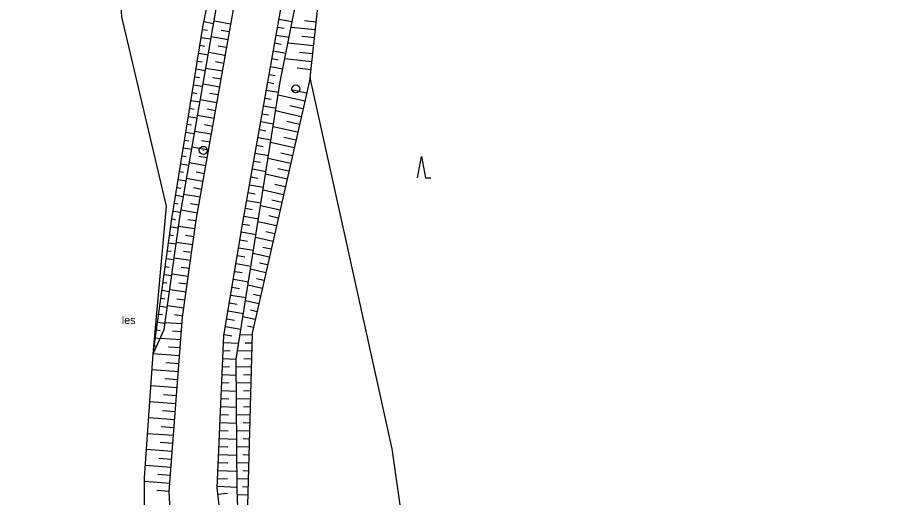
# Model space of a CAD drawing. Extents: x -762483 to -761175, y -1154655 to -1152452.
# Drawn here: x -761535.1 to -761452.1, y -1153544 to -1153499 of the extents above; entities that cross this region are included whole.
import ezdxf

# ---------------------------------------------------------------- set-up
doc = ezdxf.new("R2010")
doc.units = 0
for name, color, linetype in [('MAP_ZN_BP', 7, 'Continuous'), ('ROZHRANÍ_PLOCH', 7, 'Continuous'), ('VÝŠKOPIS', 7, 'Continuous'), ('ZELEŇ', 7, 'Continuous'), ('ZN_KULTUR', 7, 'Continuous')]:
    doc.layers.add(name, color=color, linetype=linetype)

msp = doc.modelspace()

# ---------------------------------------------------------------- linework, layer by layer
at = {"layer": 'MAP_ZN_BP'}
for centre, radius in [((-761509.05, -1153505.69), 0.375), ((-761509.05, -1153505.69), 0.0005), ((-761517.73, -1153511.451), 0.375), ((-761517.73, -1153511.451), 0.0005)]:
    msp.add_circle(centre, radius, dxfattribs=at)
at = {"layer": 'ROZHRANÍ_PLOCH'}
for points in [[(-761473.21, -1153684.07), (-761469.46, -1153679.5), (-761466.97, -1153675.46), (-761465.27, -1153671.92), (-761464.53, -1153668.61), (-761464.73, -1153664.68), (-761466, -1153658.71), (-761468.55, -1153651.77), (-761473.7, -1153641.76), (-761483.81, -1153624.91), (-761489.13, -1153616.22), (-761501.02, -1153596.18), (-761505.16, -1153588.62), (-761508.76, -1153581.79), (-761515.86, -1153566.65), (-761518.43, -1153558.82), (-761520.62, -1153549.31), (-761520.92, -1153543.45), (-761519.67, -1153527.09), (-761518.4, -1153518.01), (-761514.9, -1153498.24), (-761512.46, -1153485.54), (-761510.57, -1153476.01), (-761507.02, -1153459.49)], [(-761452.11, -1153680.09), (-761455.06, -1153677.36), (-761457.46, -1153672.86), (-761459.23, -1153668.13), (-761461.75, -1153656.48), (-761464.72, -1153649.83), (-761470.08, -1153639.37), (-761481.24, -1153620.57), (-761493.92, -1153599.29), (-761502.78, -1153583.29), (-761511.19, -1153565.87), (-761514.81, -1153554.8), (-761515.74, -1153549.15), (-761516.42, -1153543.11), (-761515.79, -1153528.81), (-761514.01, -1153518.23), (-761510.25, -1153496.92), (-761507.85, -1153485.44), (-761506.02, -1153476.2), (-761502.85, -1153460.41)]]:
    msp.add_lwpolyline(points, dxfattribs=at)
at = {"layer": 'VÝŠKOPIS'}
for p, q in [((-761517.66, -1153499.383), (-761516.761, -1153499.57)), ((-761515.142, -1153499.609), (-761516.719, -1153499.329)), ((-761510.645, -1153499.161), (-761509.385, -1153499.384)), ((-761507.151, -1153499.421), (-761508.248, -1153499.301)), ((-761517.795, -1153500.121), (-761517.339, -1153500.195)), ((-761515.273, -1153500.347), (-761516.061, -1153500.208)), ((-761510.776, -1153499.9), (-761510.154, -1153500.01)), ((-761507.232, -1153500.166), (-761509.492, -1153499.92)), ((-761517.915, -1153500.861), (-761517.012, -1153501.008)), ((-761515.404, -1153501.086), (-761516.977, -1153500.807)), ((-761510.906, -1153500.638), (-761509.678, -1153500.855)), ((-761507.314, -1153500.912), (-761508.476, -1153500.785)), ((-761518.036, -1153501.601), (-761517.588, -1153501.674)), ((-761515.535, -1153501.824), (-761516.32, -1153501.685)), ((-761511.036, -1153501.377), (-761510.431, -1153501.484)), ((-761507.395, -1153501.658), (-761509.786, -1153501.397)), ((-761518.156, -1153502.342), (-761517.269, -1153502.486)), ((-761515.665, -1153502.563), (-761517.234, -1153502.285)), ((-761511.167, -1153502.116), (-761509.971, -1153502.326)), ((-761507.476, -1153502.403), (-761508.705, -1153502.269)), ((-761518.276, -1153503.082), (-761517.837, -1153503.153)), ((-761515.796, -1153503.301), (-761516.58, -1153503.163)), ((-761511.427, -1153503.593), (-761510.265, -1153503.798)), ((-761511.297, -1153502.854), (-761510.707, -1153502.958)), ((-761507.557, -1153503.149), (-761510.08, -1153502.874)), ((-761518.397, -1153503.822), (-761517.527, -1153503.964)), ((-761515.927, -1153504.04), (-761517.492, -1153503.763)), ((-761511.558, -1153504.331), (-761510.984, -1153504.432)), ((-761507.639, -1153503.894), (-761508.933, -1153503.753)), ((-761518.517, -1153504.562), (-761518.086, -1153504.632)), ((-761516.188, -1153505.517), (-761517.749, -1153505.24)), ((-761516.058, -1153504.778), (-761516.839, -1153504.64)), ((-761511.688, -1153505.07), (-761511.118, -1153505.17)), ((-761518.758, -1153506.043), (-761518.335, -1153506.112)), ((-761518.637, -1153505.303), (-761517.784, -1153505.441)), ((-761516.319, -1153506.255), (-761517.098, -1153506.117)), ((-761511.818, -1153505.808), (-761510.666, -1153506.012)), ((-761508.051, -1153506.103), (-761509.32, -1153505.816)), ((-761518.878, -1153506.783), (-761518.042, -1153506.919)), ((-761516.45, -1153506.994), (-761518.007, -1153506.718)), ((-761511.949, -1153506.547), (-761511.366, -1153506.65)), ((-761508.217, -1153506.835), (-761510.707, -1153506.271)), ((-761518.998, -1153507.524), (-761518.584, -1153507.591)), ((-761516.58, -1153507.732), (-761517.358, -1153507.595)), ((-761512.079, -1153507.286), (-761510.902, -1153507.493)), ((-761508.548, -1153508.298), (-761510.944, -1153507.755)), ((-761508.382, -1153507.566), (-761509.604, -1153507.29)), ((-761519.119, -1153508.264), (-761518.299, -1153508.397)), ((-761516.711, -1153508.471), (-761518.264, -1153508.196)), ((-761512.209, -1153508.024), (-761511.615, -1153508.129)), ((-761519.239, -1153509.004), (-761518.833, -1153509.07)), ((-761516.842, -1153509.209), (-761517.617, -1153509.072)), ((-761512.34, -1153508.763), (-761511.138, -1153508.975)), ((-761508.879, -1153509.761), (-761511.18, -1153509.24)), ((-761508.713, -1153509.029), (-761509.888, -1153508.763)), ((-761519.359, -1153509.744), (-761518.556, -1153509.875)), ((-761516.973, -1153509.948), (-761518.521, -1153509.674)), ((-761512.6, -1153510.24), (-761511.374, -1153510.456)), ((-761512.47, -1153509.501), (-761511.863, -1153509.609)), ((-761509.044, -1153510.492), (-761510.171, -1153510.237)), ((-761519.48, -1153510.485), (-761519.082, -1153510.549)), ((-761517.103, -1153510.686), (-761517.877, -1153510.55)), ((-761512.731, -1153510.979), (-761512.111, -1153511.088)), ((-761509.21, -1153511.224), (-761511.416, -1153510.724)), ((-761519.6, -1153511.225), (-761518.814, -1153511.353)), ((-761517.234, -1153511.425), (-761518.779, -1153511.151)), ((-761512.861, -1153511.717), (-761511.61, -1153511.938)), ((-761509.375, -1153511.955), (-761510.455, -1153511.711)), ((-761519.841, -1153512.706), (-761519.071, -1153512.831)), ((-761519.72, -1153511.965), (-761519.331, -1153512.028)), ((-761517.496, -1153512.902), (-761519.036, -1153512.629)), ((-761517.365, -1153512.163), (-761518.136, -1153512.027)), ((-761512.991, -1153512.456), (-761512.359, -1153512.567)), ((-761509.541, -1153512.687), (-761511.653, -1153512.209)), ((-761519.961, -1153513.446), (-761519.58, -1153513.508)), ((-761517.626, -1153513.64), (-761518.396, -1153513.504)), ((-761513.122, -1153513.194), (-761511.845, -1153513.42)), ((-761509.707, -1153513.418), (-761510.739, -1153513.184)), ((-761520.081, -1153514.186), (-761519.329, -1153514.308)), ((-761517.757, -1153514.379), (-761519.294, -1153514.107)), ((-761513.252, -1153513.933), (-761512.608, -1153514.047)), ((-761509.872, -1153514.15), (-761511.889, -1153513.693)), ((-761520.202, -1153514.926), (-761519.83, -1153514.987)), ((-761517.888, -1153515.118), (-761518.655, -1153514.982)), ((-761513.382, -1153514.672), (-761512.081, -1153514.901)), ((-761510.203, -1153515.613), (-761512.125, -1153515.178)), ((-761510.038, -1153514.881), (-761511.022, -1153514.658)), ((-761520.322, -1153515.667), (-761519.586, -1153515.786)), ((-761518.019, -1153515.856), (-761519.551, -1153515.585)), ((-761513.512, -1153515.41), (-761512.856, -1153515.526)), ((-761520.442, -1153516.407), (-761520.079, -1153516.466)), ((-761518.149, -1153516.595), (-761518.915, -1153516.459)), ((-761513.773, -1153516.887), (-761513.104, -1153517.005)), ((-761513.643, -1153516.149), (-761512.317, -1153516.383)), ((-761510.534, -1153517.076), (-761512.361, -1153516.662)), ((-761510.369, -1153516.344), (-761511.306, -1153516.132)), ((-761520.563, -1153517.147), (-761519.844, -1153517.264)), ((-761518.28, -1153517.333), (-761519.808, -1153517.063)), ((-761513.903, -1153517.626), (-761512.553, -1153517.864)), ((-761510.7, -1153517.807), (-761511.59, -1153517.606)), ((-761520.682, -1153517.888), (-761520.322, -1153517.937)), ((-761518.409, -1153518.072), (-761519.176, -1153517.965)), ((-761514.033, -1153518.365), (-761513.351, -1153518.479)), ((-761510.865, -1153518.539), (-761512.598, -1153518.146)), ((-761520.886, -1153519.374), (-761520.526, -1153519.423)), ((-761520.784, -1153518.631), (-761520.064, -1153518.729)), ((-761518.513, -1153518.815), (-761520.046, -1153518.6)), ((-761514.157, -1153519.104), (-761512.787, -1153519.335)), ((-761511.031, -1153519.27), (-761511.873, -1153519.079)), ((-761520.987, -1153520.117), (-761520.269, -1153520.215)), ((-761518.72, -1153520.3), (-761520.252, -1153520.086)), ((-761518.616, -1153519.557), (-761519.383, -1153519.45)), ((-761514.282, -1153519.844), (-761513.593, -1153519.96)), ((-761511.196, -1153520.002), (-761512.834, -1153519.631)), ((-761521.089, -1153520.86), (-761520.73, -1153520.909)), ((-761518.824, -1153521.043), (-761519.589, -1153520.936)), ((-761514.406, -1153520.584), (-761513.023, -1153520.816)), ((-761511.362, -1153520.733), (-761512.157, -1153520.553)), ((-761521.191, -1153521.603), (-761520.475, -1153521.701)), ((-761518.928, -1153521.786), (-761520.457, -1153521.572)), ((-761514.53, -1153521.323), (-761513.835, -1153521.44)), ((-761511.527, -1153521.465), (-761513.07, -1153521.115)), ((-761521.292, -1153522.346), (-761520.935, -1153522.395)), ((-761519.032, -1153522.529), (-761519.796, -1153522.422)), ((-761514.655, -1153522.063), (-761513.258, -1153522.298)), ((-761511.859, -1153522.928), (-761513.307, -1153522.6)), ((-761511.693, -1153522.196), (-761512.441, -1153522.027)), ((-761521.394, -1153523.089), (-761520.68, -1153523.187)), ((-761519.136, -1153523.271), (-761520.662, -1153523.058)), ((-761514.904, -1153523.542), (-761513.494, -1153523.779)), ((-761514.779, -1153522.802), (-761514.078, -1153522.92)), ((-761512.024, -1153523.659), (-761512.724, -1153523.501)), ((-761521.495, -1153523.832), (-761521.139, -1153523.881)), ((-761519.24, -1153524.014), (-761520.002, -1153523.907)), ((-761515.028, -1153524.282), (-761514.32, -1153524.401)), ((-761512.19, -1153524.391), (-761513.543, -1153524.084)), ((-761521.597, -1153524.575), (-761520.886, -1153524.673)), ((-761519.344, -1153524.757), (-761520.868, -1153524.544)), ((-761515.153, -1153525.021), (-761513.73, -1153525.26)), ((-761512.355, -1153525.122), (-761513.008, -1153524.974)), ((-761521.699, -1153525.318), (-761521.343, -1153525.367)), ((-761519.551, -1153526.242), (-761521.073, -1153526.03)), ((-761519.448, -1153525.5), (-761520.209, -1153525.393)), ((-761515.277, -1153525.761), (-761514.562, -1153525.881)), ((-761512.521, -1153525.854), (-761513.779, -1153525.569)), ((-761521.902, -1153526.805), (-761521.548, -1153526.853)), ((-761521.8, -1153526.062), (-761521.091, -1153526.159)), ((-761519.655, -1153526.985), (-761520.416, -1153526.879)), ((-761515.401, -1153526.5), (-761513.966, -1153526.742)), ((-761512.686, -1153526.585), (-761513.292, -1153526.448)), ((-761522.004, -1153527.548), (-761521.296, -1153527.644)), ((-761519.719, -1153527.732), (-761521.292, -1153527.612)), ((-761515.526, -1153527.24), (-761514.805, -1153527.361)), ((-761512.852, -1153527.317), (-761514.015, -1153527.053)), ((-761522.105, -1153528.291), (-761521.772, -1153528.336)), ((-761519.776, -1153528.48), (-761520.602, -1153528.417)), ((-761515.65, -1153527.98), (-761514.202, -1153528.223)), ((-761513.017, -1153528.048), (-761513.575, -1153527.922)), ((-761522.207, -1153529.034), (-761521.763, -1153529.094)), ((-761519.833, -1153529.228), (-761521.757, -1153529.081)), ((-761515.775, -1153528.719), (-761515.047, -1153528.842)), ((-761513.145, -1153528.784), (-761514.286, -1153528.753)), ((-761522.308, -1153529.777), (-761522.197, -1153529.792)), ((-761519.89, -1153529.976), (-761520.989, -1153529.892)), ((-761515.819, -1153529.467), (-761514.41, -1153529.529)), ((-761513.166, -1153529.534), (-761513.785, -1153529.517)), ((-761519.948, -1153530.724), (-761522.411, -1153530.535)), ((-761515.885, -1153530.966), (-761514.647, -1153531.02)), ((-761515.852, -1153530.217), (-761515.19, -1153530.246)), ((-761513.186, -1153530.284), (-761514.524, -1153530.247)), ((-761513.207, -1153531.033), (-761513.925, -1153531.014)), ((-761520.005, -1153531.471), (-761521.234, -1153531.377)), ((-761515.918, -1153531.715), (-761515.281, -1153531.743)), ((-761513.227, -1153531.783), (-761514.644, -1153531.745)), ((-761520.062, -1153532.219), (-761522.515, -1153532.032)), ((-761515.951, -1153532.464), (-761514.637, -1153532.522)), ((-761513.247, -1153532.533), (-761513.942, -1153532.514)), ((-761520.119, -1153532.967), (-761521.343, -1153532.874)), ((-761515.984, -1153533.214), (-761515.307, -1153533.243)), ((-761513.268, -1153533.283), (-761514.63, -1153533.246)), ((-761520.176, -1153533.715), (-761522.62, -1153533.528)), ((-761516.017, -1153533.963), (-761514.623, -1153534.024)), ((-761513.288, -1153534.032), (-761513.956, -1153534.014)), ((-761520.29, -1153535.21), (-761522.724, -1153535.025)), ((-761520.233, -1153534.463), (-761521.452, -1153534.37)), ((-761516.05, -1153534.712), (-761515.333, -1153534.744)), ((-761513.309, -1153534.782), (-761514.617, -1153534.746)), ((-761520.348, -1153535.958), (-761521.562, -1153535.866)), ((-761516.083, -1153535.461), (-761514.61, -1153535.526)), ((-761513.329, -1153535.532), (-761513.97, -1153535.514)), ((-761520.405, -1153536.706), (-761522.828, -1153536.521)), ((-761516.116, -1153536.211), (-761515.36, -1153536.244)), ((-761513.349, -1153536.282), (-761514.603, -1153536.247)), ((-761520.462, -1153537.454), (-761521.671, -1153537.362)), ((-761516.149, -1153536.96), (-761514.596, -1153537.028)), ((-761513.37, -1153537.031), (-761513.983, -1153537.015)), ((-761520.519, -1153538.202), (-761522.932, -1153538.017)), ((-761516.215, -1153538.459), (-761514.583, -1153538.53)), ((-761516.182, -1153537.709), (-761515.386, -1153537.744)), ((-761513.39, -1153537.781), (-761514.59, -1153537.748)), ((-761520.576, -1153538.95), (-761521.78, -1153538.858)), ((-761516.248, -1153539.208), (-761515.412, -1153539.245)), ((-761513.431, -1153539.28), (-761514.577, -1153539.249)), ((-761513.411, -1153538.531), (-761513.997, -1153538.515)), ((-761520.633, -1153539.697), (-761523.036, -1153539.514)), ((-761516.281, -1153539.957), (-761514.57, -1153540.033)), ((-761513.452, -1153540.03), (-761514.011, -1153540.015)), ((-761520.69, -1153540.445), (-761521.889, -1153540.354)), ((-761516.314, -1153540.706), (-761515.439, -1153540.745)), ((-761513.472, -1153540.78), (-761514.563, -1153540.75)), ((-761520.748, -1153541.193), (-761523.141, -1153541.01)), ((-761516.347, -1153541.456), (-761514.556, -1153541.535)), ((-761513.492, -1153541.53), (-761514.024, -1153541.515)), ((-761520.862, -1153542.689), (-761523.219, -1153542.509)), ((-761520.805, -1153541.941), (-761521.999, -1153541.85)), ((-761516.38, -1153542.205), (-761515.465, -1153542.245)), ((-761513.513, -1153542.279), (-761514.55, -1153542.251)), ((-761520.919, -1153543.437), (-761522.067, -1153543.349)), ((-761516.413, -1153542.954), (-761514.543, -1153543.037)), ((-761513.533, -1153543.029), (-761514.038, -1153543.015)), ((-761516.354, -1153543.7), (-761515.444, -1153543.598)), ((-761513.554, -1153543.779), (-761514.525, -1153543.752))]:
    msp.add_line(p, q, dxfattribs=at)
for points in [[(-761522.41, -1153530.52), (-761520.68, -1153517.87), (-761517.73, -1153499.72), (-761512.59, -1153474.98), (-761507.83, -1153454.54)], [(-761522.41, -1153530.52), (-761521.38, -1153528.25), (-761519.93, -1153517.76), (-761516.46, -1153497.84), (-761512.68, -1153479.49), (-761508.08, -1153459.32)], [(-761510.51, -1153505.03), (-761506.83, -1153486.56), (-761501.96, -1153460.76)], [(-761472.39, -1153633.33), (-761479.86, -1153619.77), (-761492.52, -1153598.23), (-761505.34, -1153575.01), (-761509.58, -1153565.6), (-761513.83, -1153553.93), (-761514.33, -1153548.93), (-761514.54, -1153543.35), (-761514.65, -1153531.04), (-761510.51, -1153505.03)], [(-761507.72, -1153504.64), (-761513.14, -1153528.59), (-761513.83, -1153553.93)]]:
    msp.add_lwpolyline(points, dxfattribs=at)
at = {"layer": 'ZELEŇ'}
msp.add_line((-761523.22, -1153542.15), (-761522.41, -1153530.52), dxfattribs=at)
for points in [[(-761522.41, -1153530.52), (-761521.16, -1153516.7), (-761525.36, -1153498.92), (-761526.95, -1153474.42), (-761535, -1153440.98), (-761535.12, -1153438.71)], [(-761507.72, -1153504.64), (-761505.65, -1153485.65), (-761501.02, -1153460.93)], [(-761472.39, -1153633.33), (-761479.21, -1153619.43), (-761487.13, -1153604.92), (-761490.34, -1153596.71), (-761495.72, -1153569.61), (-761500.02, -1153539.43), (-761507.72, -1153504.64)], [(-761509.98, -1153584.09), (-761517.59, -1153566.97), (-761520.18, -1153558.87), (-761522.43, -1153550.02), (-761523.2, -1153547.66), (-761523.22, -1153542.15)]]:
    msp.add_lwpolyline(points, dxfattribs=at)
at = {"layer": 'ZN_KULTUR'}
msp.add_lwpolyline([(-761497.655, -1153514.02), (-761497.28, -1153512.02), (-761496.905, -1153514.02), (-761496.405, -1153514.02)], dxfattribs=at)

# ---------------------------------------------------------------- texts
at = {"layer": 'ZELEŇ'}
msp.add_text('les', height=0.75, dxfattribs=at).set_placement((-761525.36, -1153527.74))

doc.saveas('drawing.dxf')
